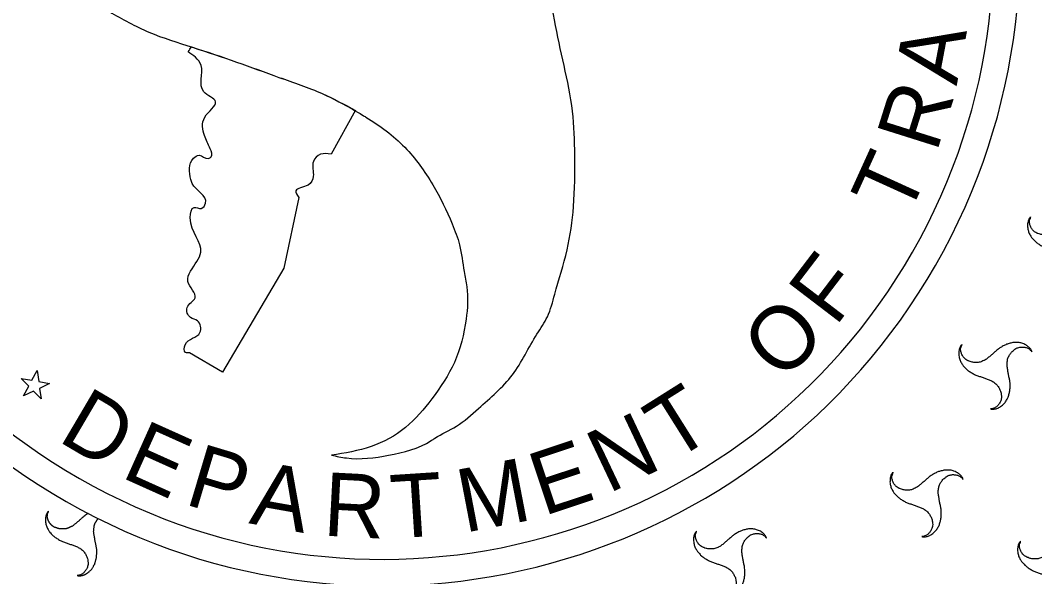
# Model space of a CAD drawing. Extents: x 1376167 to 1379209, y 761324 to 763997.
# Drawn here: x 1377746.7 to 1377830.6, y 763384 to 763430 of the extents above; entities that cross this region are included whole.
import ezdxf

# ---------------------------------------------------------------- set-up
doc = ezdxf.new("R2010")
doc.units = 0
doc.layers.add('Sheet Title CELL', color=7, linetype='Continuous')

msp = doc.modelspace()

# ---------------------------------------------------------------- linework, layer by layer
at = {"layer": 'Sheet Title CELL'}
for p, q in [((1377774.406, 763422.596), (1377772.385, 763418.946)), ((1377769.717, 763415.379), (1377768.481, 763409.53)), ((1377830.28, 763413.765), (1377830.284, 763413.754)), ((1377768.481, 763409.53), (1377763.405, 763400.906)), ((1377824.586, 763403.202), (1377824.59, 763403.191)), ((1377763.405, 763400.906), (1377760.665, 763402.507)), ((1377747.635, 763400.266), (1377748.065, 763401.064)), ((1377748.065, 763401.064), (1377748.19, 763400.144)), ((1377747.368, 763399.771), (1377746.744, 763400.391)), ((1377746.744, 763400.391), (1377747.635, 763400.266)), ((1377748.19, 763400.144), (1377749.094, 763399.977)), ((1377746.93, 763398.96), (1377747.368, 763399.771)), ((1377747.76, 763399.346), (1377746.93, 763398.96)), ((1377748.405, 763398.697), (1377747.76, 763399.346)), ((1377749.094, 763399.977), (1377748.257, 763399.576)), ((1377748.257, 763399.576), (1377748.405, 763398.697)), ((1377818.891, 763392.639), (1377818.895, 763392.628)), ((1377748.994, 763389.424), (1377748.998, 763389.413)), ((1377802.634, 763387.771), (1377802.638, 763387.76)), ((1377829.454, 763386.945), (1377829.458, 763386.934))]:
    msp.add_line(p, q, dxfattribs=at)
for centre, radius, start, end in [((1377776.67, 763435.957), 52.717, 61.67024, 241.67024), ((1377776.67, 763435.957), 50.52, 61.67024, 241.67024), ((1377776.67, 763435.957), 52.716, 241.67024, 61.67024), ((1377776.67, 763435.957), 50.52, 241.67024, 61.67024), ((1377526.551, 763577.393), 277.945, 327.34873, 327.44833)]:
    msp.add_arc(centre, radius, start, end, dxfattribs=at)
for points in [[(1377742.613, 763460.558), (1377741.775, 763459.661), (1377740.238, 763456.513), (1377739.551, 763452.836), (1377739.554, 763452.479), (1377739.534, 763450.467), (1377739.875, 763448.135), (1377740.897, 763444.335), (1377742.788, 763440.831), (1377743.625, 763439.386), (1377744.861, 763437.991), (1377747.578, 763435.195), (1377750.453, 763432.953), (1377754.041, 763430.752), (1377757.317, 763429.058), (1377760.92, 763427.807), (1377764.574, 763426.583), (1377768.079, 763425.314), (1377771.666, 763423.966), (1377774.988, 763422.193), (1377775.27, 763422.024), (1377778.485, 763419.527), (1377780.809, 763416.428), (1377782.415, 763413.184), (1377783.026, 763411.452), (1377783.398, 763409.245), (1377783.625, 763407.987), (1377783.563, 763405.304), (1377782.593, 763401.727), (1377780.739, 763398.715), (1377778.554, 763396.342), (1377775.695, 763394.76), (1377772.436, 763394.049)], [(1377772.436, 763394.049), (1377773.659, 763393.816), (1377777.155, 763394.043), (1377780.688, 763395.263), (1377780.967, 763395.45), (1377782.766, 763396.45), (1377784.587, 763397.918), (1377787.399, 763400.698), (1377789.433, 763404.075), (1377790.295, 763405.509), (1377790.904, 763407.364), (1377791.926, 763411.038), (1377792.456, 763414.622), (1377792.559, 763418.862), (1377792.378, 763422.51), (1377791.67, 763426.3), (1377790.877, 763430.065), (1377790.249, 763433.741), (1377789.645, 763437.527), (1377789.489, 763441.286), (1377789.535, 763441.669), (1377790.079, 763445.707), (1377791.586, 763449.226), (1377793.552, 763452.214), (1377794.778, 763453.665), (1377796.518, 763455.017), (1377797.49, 763455.931), (1377799.842, 763457.166), (1377803.415, 763458.097), (1377806.922, 763458.017), (1377810.102, 763457.297), (1377812.902, 763455.61), (1377815.12, 763453.171)], [(1377760.831, 763427.838), (1377760.92, 763427.807), (1377764.574, 763426.583), (1377768.079, 763425.314), (1377771.666, 763423.966), (1377774.399, 763422.582)], [(1377760.665, 763402.507), (1377760.352, 763402.552), (1377760.302, 763403.183), (1377761.542, 763404.2), (1377761.334, 763405.164), (1377760.756, 763405.441), (1377760.474, 763406.267), (1377761.134, 763407.065), (1377760.54, 763408.433), (1377760.762, 763409.272), (1377761.607, 763410.84), (1377760.738, 763413.705), (1377761.05, 763414.548), (1377761.649, 763414.474), (1377762.005, 763414.903), (1377760.895, 763416.531), (1377760.786, 763416.856), (1377760.994, 763418.625), (1377761.477, 763418.862), (1377762.224, 763418.602), (1377762.473, 763418.734), (1377762.388, 763419.4), (1377761.912, 763420.492), (1377761.938, 763422.022), (1377762.837, 763423.295), (1377761.849, 763424.129), (1377761.636, 763426.303), (1377761.168, 763426.981), (1377760.552, 763427.42)], [(1377772.385, 763418.946), (1377771.519, 763418.951), (1377770.927, 763418.347), (1377770.917, 763417.11), (1377770.482, 763416.404), (1377769.475, 763415.917), (1377769.717, 763415.379)], [(1377830.284, 763413.754), (1377830.217, 763413.682), (1377830.094, 763413.43), (1377830.039, 763413.136), (1377830.04, 763413.108), (1377830.038, 763412.947), (1377830.065, 763412.76), (1377830.147, 763412.456), (1377830.298, 763412.176), (1377830.365, 763412.06), (1377830.464, 763411.949), (1377830.682, 763411.725), (1377830.911, 763411.546), (1377831.199, 763411.37), (1377831.461, 763411.234), (1377831.749, 763411.134), (1377832.041, 763411.036), (1377832.322, 763410.934), (1377832.609, 763410.827), (1377832.874, 763410.685), (1377832.897, 763410.671), (1377833.154, 763410.471), (1377833.34, 763410.224), (1377833.468, 763409.964), (1377833.517, 763409.826), (1377833.547, 763409.649), (1377833.565, 763409.548), (1377833.56, 763409.334), (1377833.483, 763409.047), (1377833.334, 763408.807), (1377833.16, 763408.617), (1377832.931, 763408.49), (1377832.67, 763408.433)], [(1377836.085, 763413.163), (1377836.056, 763413.252), (1377835.9, 763413.487), (1377835.673, 763413.682), (1377835.65, 763413.699), (1377835.509, 763413.778), (1377835.333, 763413.848), (1377835.03, 763413.932), (1377834.712, 763413.937), (1377834.578, 763413.94), (1377834.429, 763413.909), (1377834.128, 763413.833), (1377833.858, 763413.724), (1377833.564, 763413.562), (1377833.317, 763413.402), (1377833.082, 763413.203), (1377832.853, 763413), (1377832.627, 763412.809), (1377832.386, 763412.611), (1377832.132, 763412.454), (1377832.108, 763412.443), (1377831.804, 763412.317), (1377831.497, 763412.281), (1377831.209, 763412.297), (1377831.068, 763412.328), (1377830.898, 763412.391), (1377830.799, 763412.423), (1377830.619, 763412.537), (1377830.408, 763412.747), (1377830.275, 763412.994), (1377830.199, 763413.24), (1377830.204, 763413.503), (1377830.284, 763413.754), (1377830.28, 763413.765)], [(1377824.59, 763403.191), (1377824.523, 763403.119), (1377824.4, 763402.868), (1377824.345, 763402.573), (1377824.345, 763402.545), (1377824.343, 763402.384), (1377824.371, 763402.197), (1377824.453, 763401.893), (1377824.604, 763401.613), (1377824.671, 763401.497), (1377824.77, 763401.386), (1377824.987, 763401.162), (1377825.217, 763400.983), (1377825.504, 763400.807), (1377825.766, 763400.671), (1377826.054, 763400.571), (1377826.347, 763400.473), (1377826.627, 763400.372), (1377826.914, 763400.264), (1377827.18, 763400.122), (1377827.202, 763400.108), (1377827.46, 763399.909), (1377827.645, 763399.661), (1377827.774, 763399.401), (1377827.823, 763399.263), (1377827.853, 763399.086), (1377827.871, 763398.986), (1377827.866, 763398.771), (1377827.788, 763398.485), (1377827.64, 763398.244), (1377827.465, 763398.054), (1377827.236, 763397.927), (1377826.976, 763397.871)], [(1377830.39, 763402.6), (1377830.362, 763402.69), (1377830.206, 763402.924), (1377829.979, 763403.119), (1377829.955, 763403.136), (1377829.814, 763403.215), (1377829.638, 763403.286), (1377829.335, 763403.369), (1377829.017, 763403.375), (1377828.884, 763403.377), (1377828.735, 763403.346), (1377828.434, 763403.27), (1377828.164, 763403.162), (1377827.869, 763403), (1377827.622, 763402.839), (1377827.387, 763402.64), (1377827.158, 763402.437), (1377826.932, 763402.247), (1377826.692, 763402.048), (1377826.438, 763401.891), (1377826.413, 763401.88), (1377826.11, 763401.754), (1377825.802, 763401.718), (1377825.514, 763401.734), (1377825.373, 763401.765), (1377825.204, 763401.828), (1377825.105, 763401.86), (1377824.925, 763401.974), (1377824.713, 763402.185), (1377824.58, 763402.431), (1377824.505, 763402.678), (1377824.51, 763402.94), (1377824.59, 763403.191), (1377824.586, 763403.202)], [(1377826.976, 763397.871), (1377827.073, 763397.852), (1377827.353, 763397.87), (1377827.636, 763397.968), (1377827.658, 763397.983), (1377827.802, 763398.063), (1377827.948, 763398.18), (1377828.173, 763398.402), (1377828.335, 763398.673), (1377828.404, 763398.787), (1377828.453, 763398.936), (1377828.535, 763399.23), (1377828.577, 763399.516), (1377828.585, 763399.856), (1377828.571, 763400.147), (1377828.514, 763400.451), (1377828.451, 763400.752), (1377828.401, 763401.046), (1377828.352, 763401.349), (1377828.34, 763401.649), (1377828.344, 763401.68), (1377828.387, 763402.003), (1377828.508, 763402.285), (1377828.665, 763402.524), (1377828.763, 763402.64), (1377828.902, 763402.748), (1377828.98, 763402.821), (1377829.168, 763402.92), (1377829.454, 763402.994), (1377829.735, 763402.988), (1377829.989, 763402.93), (1377830.213, 763402.795), (1377830.39, 763402.6)], [(1377818.895, 763392.628), (1377818.828, 763392.557), (1377818.705, 763392.305), (1377818.65, 763392.011), (1377818.651, 763391.982), (1377818.649, 763391.821), (1377818.676, 763391.635), (1377818.758, 763391.331), (1377818.909, 763391.05), (1377818.976, 763390.935), (1377819.075, 763390.823), (1377819.292, 763390.599), (1377819.522, 763390.42), (1377819.809, 763390.244), (1377820.072, 763390.108), (1377820.36, 763390.008), (1377820.652, 763389.91), (1377820.933, 763389.809), (1377821.219, 763389.701), (1377821.485, 763389.559), (1377821.508, 763389.546), (1377821.765, 763389.346), (1377821.951, 763389.098), (1377822.079, 763388.838), (1377822.128, 763388.7), (1377822.158, 763388.523), (1377822.176, 763388.423), (1377822.171, 763388.208), (1377822.094, 763387.922), (1377821.945, 763387.681), (1377821.771, 763387.491), (1377821.542, 763387.365), (1377821.281, 763387.308)], [(1377824.696, 763392.038), (1377824.667, 763392.127), (1377824.511, 763392.361), (1377824.284, 763392.556), (1377824.26, 763392.573), (1377824.12, 763392.652), (1377823.943, 763392.723), (1377823.641, 763392.807), (1377823.323, 763392.812), (1377823.189, 763392.814), (1377823.04, 763392.784), (1377822.739, 763392.707), (1377822.469, 763392.599), (1377822.175, 763392.437), (1377821.927, 763392.276), (1377821.693, 763392.077), (1377821.464, 763391.874), (1377821.238, 763391.684), (1377820.997, 763391.485), (1377820.743, 763391.328), (1377820.719, 763391.317), (1377820.415, 763391.191), (1377820.108, 763391.155), (1377819.82, 763391.172), (1377819.678, 763391.202), (1377819.509, 763391.265), (1377819.41, 763391.297), (1377819.23, 763391.411), (1377819.019, 763391.622), (1377818.886, 763391.868), (1377818.81, 763392.115), (1377818.815, 763392.378), (1377818.895, 763392.628), (1377818.891, 763392.639)], [(1377821.281, 763387.308), (1377821.379, 763387.289), (1377821.659, 763387.307), (1377821.941, 763387.405), (1377821.964, 763387.42), (1377822.107, 763387.5), (1377822.253, 763387.617), (1377822.478, 763387.84), (1377822.641, 763388.11), (1377822.71, 763388.225), (1377822.759, 763388.373), (1377822.84, 763388.667), (1377822.883, 763388.954), (1377822.891, 763389.293), (1377822.876, 763389.585), (1377822.82, 763389.888), (1377822.756, 763390.189), (1377822.706, 763390.483), (1377822.658, 763390.786), (1377822.645, 763391.087), (1377822.649, 763391.117), (1377822.693, 763391.44), (1377822.813, 763391.722), (1377822.97, 763391.961), (1377823.068, 763392.077), (1377823.208, 763392.185), (1377823.285, 763392.258), (1377823.474, 763392.357), (1377823.759, 763392.432), (1377824.04, 763392.425), (1377824.294, 763392.368), (1377824.518, 763392.233), (1377824.696, 763392.038)], [(1377748.998, 763389.413), (1377748.931, 763389.341), (1377748.808, 763389.089), (1377748.753, 763388.795), (1377748.753, 763388.767), (1377748.751, 763388.606), (1377748.779, 763388.419), (1377748.86, 763388.115), (1377749.012, 763387.835), (1377749.079, 763387.719), (1377749.178, 763387.608), (1377749.395, 763387.384), (1377749.625, 763387.204), (1377749.912, 763387.028), (1377750.174, 763386.893), (1377750.462, 763386.793), (1377750.755, 763386.695), (1377751.035, 763386.593), (1377751.322, 763386.486), (1377751.588, 763386.344), (1377751.61, 763386.33), (1377751.868, 763386.13), (1377752.053, 763385.882), (1377752.182, 763385.623), (1377752.231, 763385.484), (1377752.261, 763385.308), (1377752.279, 763385.207), (1377752.274, 763384.993), (1377752.196, 763384.706), (1377752.048, 763384.465), (1377751.873, 763384.276), (1377751.644, 763384.149), (1377751.384, 763384.092)], [(1377802.638, 763387.76), (1377802.571, 763387.688), (1377802.448, 763387.437), (1377802.393, 763387.142), (1377802.393, 763387.114), (1377802.392, 763386.953), (1377802.419, 763386.766), (1377802.501, 763386.462), (1377802.652, 763386.182), (1377802.719, 763386.066), (1377802.818, 763385.955), (1377803.035, 763385.731), (1377803.265, 763385.552), (1377803.552, 763385.376), (1377803.814, 763385.24), (1377804.103, 763385.14), (1377804.395, 763385.042), (1377804.675, 763384.941), (1377804.962, 763384.833), (1377805.228, 763384.691), (1377805.25, 763384.677), (1377805.508, 763384.478), (1377805.694, 763384.23), (1377805.822, 763383.97), (1377805.871, 763383.832), (1377805.901, 763383.655), (1377805.919, 763383.555), (1377805.914, 763383.34), (1377805.836, 763383.054), (1377805.688, 763382.813), (1377805.513, 763382.623), (1377805.284, 763382.496), (1377805.024, 763382.44)], [(1377808.439, 763387.169), (1377808.41, 763387.259), (1377808.254, 763387.493), (1377808.027, 763387.688), (1377808.003, 763387.705), (1377807.862, 763387.784), (1377807.686, 763387.855), (1377807.383, 763387.938), (1377807.065, 763387.944), (1377806.932, 763387.946), (1377806.783, 763387.915), (1377806.482, 763387.839), (1377806.212, 763387.731), (1377805.917, 763387.569), (1377805.67, 763387.408), (1377805.435, 763387.209), (1377805.206, 763387.006), (1377804.98, 763386.816), (1377804.74, 763386.617), (1377804.486, 763386.46), (1377804.462, 763386.449), (1377804.158, 763386.323), (1377803.85, 763386.287), (1377803.562, 763386.303), (1377803.421, 763386.334), (1377803.252, 763386.397), (1377803.153, 763386.429), (1377802.973, 763386.543), (1377802.761, 763386.754), (1377802.628, 763387), (1377802.553, 763387.247), (1377802.558, 763387.509), (1377802.638, 763387.76), (1377802.634, 763387.771)], [(1377805.024, 763382.44), (1377805.122, 763382.421), (1377805.401, 763382.439), (1377805.684, 763382.537), (1377805.706, 763382.552), (1377805.85, 763382.632), (1377805.996, 763382.749), (1377806.221, 763382.971), (1377806.383, 763383.242), (1377806.452, 763383.356), (1377806.501, 763383.505), (1377806.583, 763383.799), (1377806.625, 763384.085), (1377806.634, 763384.425), (1377806.619, 763384.716), (1377806.562, 763385.02), (1377806.499, 763385.321), (1377806.449, 763385.615), (1377806.401, 763385.918), (1377806.388, 763386.218), (1377806.392, 763386.249), (1377806.435, 763386.572), (1377806.556, 763386.854), (1377806.713, 763387.093), (1377806.811, 763387.209), (1377806.95, 763387.317), (1377807.028, 763387.39), (1377807.216, 763387.489), (1377807.502, 763387.563), (1377807.783, 763387.557), (1377808.037, 763387.499), (1377808.261, 763387.364), (1377808.439, 763387.169)], [(1377829.458, 763386.934), (1377829.391, 763386.862), (1377829.268, 763386.61), (1377829.213, 763386.316), (1377829.213, 763386.288), (1377829.212, 763386.127), (1377829.239, 763385.94), (1377829.321, 763385.636), (1377829.472, 763385.356), (1377829.539, 763385.24), (1377829.638, 763385.129), (1377829.855, 763384.905), (1377830.085, 763384.726), (1377830.372, 763384.549), (1377830.634, 763384.414), (1377830.923, 763384.314), (1377831.215, 763384.216), (1377831.495, 763384.114), (1377831.782, 763384.007), (1377832.048, 763383.865), (1377832.071, 763383.851), (1377832.328, 763383.651), (1377832.514, 763383.404), (1377832.642, 763383.144), (1377832.691, 763383.005), (1377832.721, 763382.829), (1377832.739, 763382.728), (1377832.734, 763382.514), (1377832.656, 763382.227), (1377832.508, 763381.986), (1377832.333, 763381.797), (1377832.105, 763381.67), (1377831.844, 763381.613)], [(1377835.259, 763386.343), (1377835.23, 763386.432), (1377835.074, 763386.667), (1377834.847, 763386.862), (1377834.823, 763386.879), (1377834.682, 763386.957), (1377834.506, 763387.028), (1377834.203, 763387.112), (1377833.885, 763387.117), (1377833.752, 763387.12), (1377833.603, 763387.089), (1377833.302, 763387.013), (1377833.032, 763386.904), (1377832.737, 763386.742), (1377832.49, 763386.582), (1377832.255, 763386.383), (1377832.027, 763386.18), (1377831.8, 763385.989), (1377831.56, 763385.791), (1377831.306, 763385.634), (1377831.282, 763385.623), (1377830.978, 763385.497), (1377830.67, 763385.461), (1377830.382, 763385.477), (1377830.241, 763385.508), (1377830.072, 763385.57), (1377829.973, 763385.603), (1377829.793, 763385.717), (1377829.581, 763385.927), (1377829.449, 763386.174), (1377829.373, 763386.42), (1377829.378, 763386.683), (1377829.458, 763386.934), (1377829.454, 763386.945)]]:
    msp.add_spline(points, degree=3, dxfattribs=at)
for points in [[(1377752.28, 763389.223), (1377752.279, 763389.222), (1377752.278, 763389.222), (1377752.277, 763389.221), (1377752.235, 763389.196), (1377752.193, 763389.17), (1377752.151, 763389.145), (1377752.13, 763389.132), (1377752.11, 763389.118), (1377752.089, 763389.104), (1377752.069, 763389.09), (1377752.049, 763389.076), (1377752.03, 763389.06), (1377751.99, 763389.029), (1377751.95, 763388.996), (1377751.911, 763388.963), (1377751.872, 763388.929), (1377751.834, 763388.896), (1377751.795, 763388.862), (1377751.719, 763388.794), (1377751.643, 763388.725), (1377751.566, 763388.659), (1377751.492, 763388.594), (1377751.416, 763388.532), (1377751.34, 763388.468), (1377751.26, 763388.401), (1377751.18, 763388.335), (1377751.1, 763388.27), (1377751.022, 763388.207), (1377750.936, 763388.155), (1377750.846, 763388.113), (1377750.838, 763388.109), (1377750.83, 763388.105), (1377750.821, 763388.102), (1377750.772, 763388.08), (1377750.722, 763388.058), (1377750.672, 763388.036), (1377750.647, 763388.026), (1377750.621, 763388.015), (1377750.596, 763388.005), (1377750.57, 763387.995), (1377750.544, 763387.985), (1377750.518, 763387.976), (1377750.468, 763387.958), (1377750.417, 763387.948), (1377750.365, 763387.945), (1377750.313, 763387.941), (1377750.262, 763387.94), (1377750.21, 763387.94), (1377750.162, 763387.94), (1377750.114, 763387.941), (1377750.066, 763387.942), (1377750.018, 763387.944), (1377749.97, 763387.949), (1377749.922, 763387.956), (1377749.874, 763387.963), (1377749.827, 763387.972), (1377749.781, 763387.987), (1377749.767, 763387.991), (1377749.752, 763387.996), (1377749.738, 763388.002), (1377749.724, 763388.007), (1377749.71, 763388.012), (1377749.696, 763388.018), (1377749.682, 763388.023), (1377749.668, 763388.028), (1377749.654, 763388.034), (1377749.64, 763388.039), (1377749.626, 763388.044), (1377749.612, 763388.049), (1377749.579, 763388.061), (1377749.545, 763388.07), (1377749.513, 763388.082), (1377749.479, 763388.094), (1377749.448, 763388.111), (1377749.419, 763388.131), (1377749.404, 763388.141), (1377749.39, 763388.151), (1377749.375, 763388.162), (1377749.361, 763388.173), (1377749.347, 763388.184), (1377749.333, 763388.196), (1377749.313, 763388.211), (1377749.294, 763388.227), (1377749.275, 763388.243), (1377749.256, 763388.259), (1377749.238, 763388.276), (1377749.22, 763388.294), (1377749.202, 763388.311), (1377749.185, 763388.329), (1377749.168, 763388.347), (1377749.152, 763388.366), (1377749.136, 763388.386), (1377749.121, 763388.406), (1377749.094, 763388.444), (1377749.069, 763388.484), (1377749.047, 763388.525), (1377749.026, 763388.567), (1377749.006, 763388.609), (1377748.988, 763388.653), (1377748.972, 763388.693), (1377748.957, 763388.733), (1377748.943, 763388.775), (1377748.93, 763388.815), (1377748.92, 763388.857), (1377748.913, 763388.899), (1377748.909, 763388.921), (1377748.906, 763388.943), (1377748.906, 763388.965), (1377748.905, 763388.987), (1377748.905, 763389.009), (1377748.906, 763389.031), (1377748.907, 763389.053), (1377748.909, 763389.075), (1377748.911, 763389.097), (1377748.913, 763389.119), (1377748.915, 763389.14), (1377748.918, 763389.162), (1377748.921, 763389.184), (1377748.928, 763389.205), (1377748.937, 763389.225), (1377748.947, 763389.247), (1377748.959, 763389.267), (1377748.969, 763389.288), (1377748.978, 763389.309), (1377748.987, 763389.329), (1377748.995, 763389.351), (1377748.999, 763389.361), (1377749, 763389.371), (1377749, 763389.382), (1377749.001, 763389.392), (1377749.001, 763389.403), (1377748.998, 763389.413), (1377748.997, 763389.417), (1377748.995, 763389.42), (1377748.994, 763389.424)], [(1377751.384, 763384.092), (1377751.416, 763384.081), (1377751.448, 763384.074), (1377751.481, 763384.073), (1377751.574, 763384.071), (1377751.669, 763384.074), (1377751.761, 763384.092), (1377751.786, 763384.097), (1377751.81, 763384.102), (1377751.835, 763384.108), (1377751.859, 763384.115), (1377751.883, 763384.121), (1377751.906, 763384.129), (1377751.954, 763384.145), (1377752, 763384.164), (1377752.044, 763384.189), (1377752.052, 763384.194), (1377752.058, 763384.2), (1377752.066, 763384.204), (1377752.078, 763384.211), (1377752.09, 763384.218), (1377752.102, 763384.224), (1377752.114, 763384.231), (1377752.126, 763384.237), (1377752.138, 763384.243), (1377752.151, 763384.25), (1377752.163, 763384.256), (1377752.175, 763384.263), (1377752.187, 763384.269), (1377752.199, 763384.277), (1377752.21, 763384.284), (1377752.262, 763384.319), (1377752.308, 763384.361), (1377752.356, 763384.402), (1377752.436, 763384.471), (1377752.526, 763384.534), (1377752.581, 763384.624), (1377752.635, 763384.714), (1377752.689, 763384.804), (1377752.743, 763384.894), (1377752.766, 763384.932), (1377752.789, 763384.971), (1377752.812, 763385.009), (1377752.839, 763385.054), (1377752.846, 763385.107), (1377752.861, 763385.157), (1377752.89, 763385.255), (1377752.919, 763385.352), (1377752.943, 763385.451), (1377752.966, 763385.546), (1377752.978, 763385.641), (1377752.985, 763385.738), (1377752.993, 763385.851), (1377752.995, 763385.964), (1377752.993, 763386.077), (1377752.992, 763386.175), (1377752.994, 763386.272), (1377752.979, 763386.369), (1377752.963, 763386.471), (1377752.943, 763386.571), (1377752.922, 763386.672), (1377752.902, 763386.773), (1377752.877, 763386.872), (1377752.859, 763386.973), (1377752.841, 763387.071), (1377752.825, 763387.169), (1377752.809, 763387.267), (1377752.792, 763387.368), (1377752.776, 763387.469), (1377752.76, 763387.57), (1377752.745, 763387.67), (1377752.737, 763387.771), (1377752.748, 763387.871), (1377752.749, 763387.881), (1377752.75, 763387.892), (1377752.752, 763387.902), (1377752.765, 763388.01), (1377752.779, 763388.117), (1377752.795, 763388.225), (1377752.802, 763388.275), (1377752.82, 763388.324), (1377752.842, 763388.37), (1377752.853, 763388.393), (1377752.864, 763388.416), (1377752.877, 763388.439), (1377752.89, 763388.461), (1377752.902, 763388.484), (1377752.916, 763388.506), (1377752.94, 763388.547), (1377752.965, 763388.588), (1377752.991, 763388.628), (1377753.017, 763388.668), (1377753.044, 763388.707), (1377753.073, 763388.745), (1377753.086, 763388.763), (1377753.099, 763388.78), (1377753.113, 763388.798)]]:
    msp.add_open_spline(points, degree=3, dxfattribs=at)

# ---------------------------------------------------------------- texts
for s, height, rotation, p in [('A', 5.24, 79.25852, (1377824.159, 763424.565)), ('R', 5.26, 72.50539, (1377822.492, 763419.003)), ('T', 5.239, 65.54877, (1377820.087, 763413.554)), ('F', 5.251, 52.63954, (1377814.127, 763404.607)), ('O', 5.253, 45.47431, (1377809.735, 763400.017)), ('D', 5.257, 329.52324, (1377749.67, 763395.282)), ('T', 5.248, 32.17062, (1377800.661, 763393.424)), ('E', 5.234, 335.81113, (1377754.897, 763392.268)), ('N', 5.267, 25.32862, (1377795.324, 763390.834)), ('E', 5.242, 18.35708, (1377789.961, 763388.986)), ('P', 5.257, 343.34352, (1377760.148, 763390.023)), ('M', 5.242, 10.8903, (1377783.417, 763387.615)), ('A', 5.249, 349.93609, (1377765.53, 763388.417)), ('R', 5.256, 357.00473, (1377771.672, 763387.396)), ('T', 5.252, 3.65526, (1377777.467, 763387.148))]:
    msp.add_text(s, height=height, rotation=rotation, dxfattribs=at).set_placement(p)

doc.saveas('drawing.dxf')
